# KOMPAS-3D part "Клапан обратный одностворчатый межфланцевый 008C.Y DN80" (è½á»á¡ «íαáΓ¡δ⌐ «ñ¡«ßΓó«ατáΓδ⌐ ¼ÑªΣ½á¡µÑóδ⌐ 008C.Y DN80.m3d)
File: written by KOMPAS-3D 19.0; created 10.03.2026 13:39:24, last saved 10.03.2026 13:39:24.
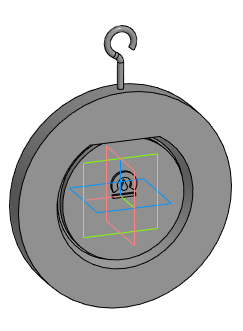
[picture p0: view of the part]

Document properties: Автор: Евгений; Полное имя файла: E:\Dendor\3D для проектировщиков\5.1 Тип 008C. Клапан обратный одностворчатый межфланцевый\stp_Клапан обратный одностворчатый межфланцевый 008C.Y\Клапан обратный одностворчатый межфланцевый 008C.Y DN80.m3d

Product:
- Part/product: Клапан обратный одностворчатый межфланцевый 008C.Y DN80

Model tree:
1. Операция без истории:1  (labels: Клапан обратный одностворчатый межфланцевый 008C.Y DN80)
